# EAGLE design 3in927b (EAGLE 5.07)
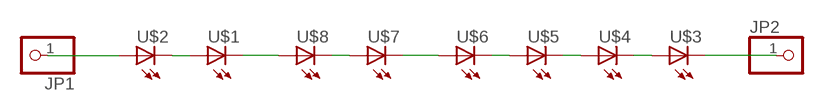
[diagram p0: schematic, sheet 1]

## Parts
JP1  PINHD-1X11X0.4  [1X01]
JP2  PINHD-1X11X0.4  [1X01]
U$1  LEDSMT1206  [1206]
U$2  LEDSMT1206  [1206]
U$3  LEDSMT1206  [1206]
U$4  LEDSMT1206  [1206]
U$5  LEDSMT1206  [1206]
U$6  LEDSMT1206  [1206]
U$7  LEDSMT1206  [1206]
U$8  LEDSMT1206  [1206]

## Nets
N$1: JP1.1 U$2.A
N$3: U$1.A U$2.C
N$4: U$6.A U$7.C
N$6: JP2.1 U$3.C
N$7: U$4.A U$5.C
N$8: U$3.A U$4.C
N$9: U$1.C U$8.A
N$10: U$7.A U$8.C
N$11: U$5.A U$6.C

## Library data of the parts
JP1 JP2 = pinhead:PINHD-1X1: PIN HEADER
U$1-U$8 = led(2):LED: LED

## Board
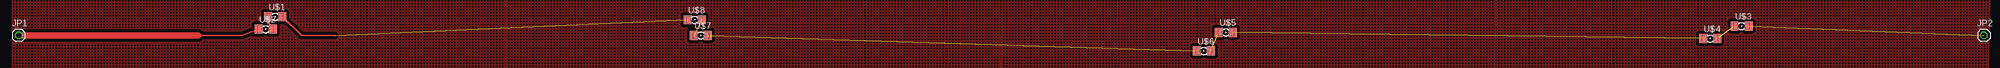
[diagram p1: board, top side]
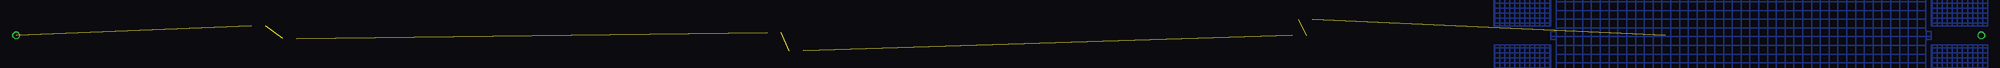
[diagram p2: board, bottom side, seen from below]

No outline drawn. Coordinates in mm, seen from the top.
Copper layers (1*16): Top 0.035mm / dielectric 1.5mm / Bottom 0.035mm
Design rules "default": minimum track width 10mil, minimum drill 24mil, track to track 8mil, track to pad 8mil, pad to pad 8mil, via to via 8mil, smd to smd 8mil, copper to edge 40mil, drill to drill 8mil, minimum pad ring 10mil, minimum via ring 8mil, stop-mask expansion 4mil, vias tented up to drill 0mil, thermal gap 10mil

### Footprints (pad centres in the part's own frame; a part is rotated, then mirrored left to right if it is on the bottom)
1X01 = drill 1.016 octagon: 1 0,0
1206 = smd 1.6 x 1.803: A -1.422,0; C 1.422,0

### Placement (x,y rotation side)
JP1  1.27,12.7 0 top
JP2  398.2,12.7 0 top
U$1  53.05,16.51 0 top
U$2  51.14,13.97 0 top
U$3  349.25,14.61 0 top
U$4  342.9,12.06 0 top
U$5  245.11,13.34 0 top
U$6  240.66,9.53 0 top
U$7  139.06,12.7 0 top
U$8  137.79,15.88 0 top

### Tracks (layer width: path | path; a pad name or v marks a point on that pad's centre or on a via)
N$1
  Top 0.305: 37.59,12.7 46.35,12.7 U$2.A
  Top 1.27: JP1.1 37.59,12.7
N$2
  pour Top (isolate 0.61, hatched): 0,25.4 99.75,25.4 99.75,0 0,0
  pour Bottom (isolate 0.813, rank 2, hatched): 11.43,25.4 88.27,25.4 88.27,0 11.43,0
  pour Top (isolate 0.61, hatched): 99.75,25.4 200.08,25.4 199.49,0 99.75,0
  pour Top (isolate 0.61, hatched): 200.03,25.4 299.77,25.4 299.24,0 199.49,0
  pour Top (isolate 0.61, hatched): 299.72,25.4 399.47,25.4 398.98,0 299.24,0
N$3
  Top 0.305: U$2.C 51.75,15.24 U$1.A
N$4  (1 unrouted)
N$5
  pour Bottom (hatched): 0,25.4 11.43,25.4 11.43,14.61 0,14.61
  pour Bottom (hatched): 0,10.79 11.43,10.79 11.43,0 0,0
  pour Bottom (hatched): 88.27,10.79 99.69,10.79 99.69,0 88.27,0
  pour Bottom (hatched): 88.27,25.4 99.75,25.4 99.75,14.61 88.27,14.61
N$6  (1 unrouted)
N$7  (1 unrouted)
N$8  (1 unrouted)
N$9  (1 unrouted)
  Top 0.305: 65.15,12.7 58.42,12.7 U$1.C
N$10  (1 unrouted)
N$11  (1 unrouted)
